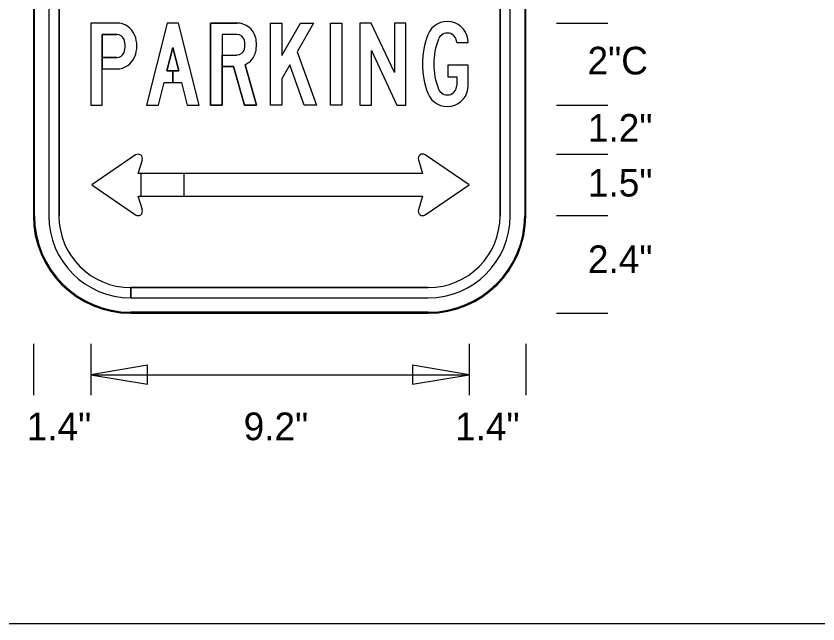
# Model space of a CAD drawing. Extents: x 0 to 770, y 0 to 495.
# Drawn here: x 85.2 to 186.6, y 330 to 406.9 of the extents above; entities that cross this region are included whole.
import ezdxf

# ---------------------------------------------------------------- set-up
doc = ezdxf.new("R2010")
doc.units = 0
for name, color, linetype in [('Dimension', 7, 'Continuous'), ('GSBWFill', 7, 'Continuous'), ('GSColorFill', 7, 'Continuous'), ('GSDims', 7, 'Continuous'), ('GSOutline', 7, 'Continuous'), ('SheetLines_dp', 7, 'Continuous'), ('TextStructures', 7, 'Continuous')]:
    doc.layers.add(name, color=color, linetype=linetype)

msp = doc.modelspace()

# ---------------------------------------------------------------- linework, layer by layer
at = {"layer": 'Dimension'}
for points in [[(94.64, 361.54), (101.81, 360.33), (101.81, 362.76)], [(142.5, 361.54), (135.33, 362.76), (135.33, 360.33)]]:
    msp.add_lwpolyline(points, close=True, dxfattribs=at)
at = {"layer": 'GSBWFill'}
for p, q in [((87.37, 450.45), (87.37, 381.66)), ((89.32, 450.45), (89.32, 381.66)), ((90.62, 381.66), (90.62, 450.45)), ((146.43, 450.45), (146.43, 381.66)), ((147.72, 381.66), (147.72, 450.45)), ((149.67, 381.66), (149.67, 450.45)), ((140.95, 403.6), (142.4, 403.6)), ((113.13, 402.01), (113.13, 402.01)), ((140.95, 399.26), (140.95, 398.14)), ((99.7, 371.28), (99.7, 372.58)), ((137.34, 372.58), (99.71, 372.58)), ((99.71, 372.58), (99.71, 371.28)), ((99.71, 371.28), (137.34, 371.28)), ((99.7, 369.33), (137.34, 369.33))]:
    msp.add_line(p, q, dxfattribs=at)
for points in [[(97.93, 406.06), (94.64, 406.06), (94.64, 395.68), (96.09, 395.68), (96.09, 404.61), (97.93, 404.61)], [(113.13, 404.61), (111.25, 404.61), (111.25, 395.68), (109.8, 395.68), (109.8, 406.06), (113.13, 406.06)], [(114.16, 400.78), (115.61, 395.68), (114.1, 395.68), (112.71, 400.56), (111.25, 400.56), (111.25, 402.01), (113.13, 402.01)], [(97.93, 401.7), (96.09, 401.7), (96.09, 400.25), (97.93, 400.25)], [(142.4, 398.14), (142.4, 400.71), (139.81, 400.71), (139.81, 399.26), (140.95, 399.26)], [(100.3, 389.37), (94.76, 385.57), (100.3, 381.77)], [(106.44, 384.13), (106.44, 387.02), (100.63, 387.02), (101.16, 388.74)], [(136.1, 388.74), (136.63, 387.02), (100.97, 387.02)], [(136.96, 381.78), (142.5, 385.58), (136.96, 389.37)], [(100.97, 387.02), (100.97, 384.13), (136.63, 384.13), (136.1, 382.41)], [(101.16, 382.4), (100.63, 384.13), (106.44, 384.13)]]:
    msp.add_lwpolyline(points, dxfattribs=at)
for points in [[(105.02, 399.99), (104.28, 399.99), (105.02, 402.97), (105.77, 399.99), (105.02, 399.99), (105.02, 398.53), (106.13, 398.53), (106.85, 395.68), (108.34, 395.68), (105.75, 406.06), (104.3, 406.06), (101.7, 395.68), (103.2, 395.68), (103.91, 398.53), (105.02, 398.53)], [(119.83, 400.76), (118.83, 399), (118.83, 395.68), (117.38, 395.68), (117.38, 406.06), (118.83, 406.06), (118.83, 401.95), (121.16, 406.06), (122.83, 406.06), (120.77, 402.43), (123.19, 395.68), (121.65, 395.68)], [(124.96, 406.06), (126.41, 406.06), (126.41, 395.68), (124.96, 395.68)], [(133.37, 395.68), (134.51, 395.68), (134.51, 406.06), (133.06, 406.06), (133.06, 399.79), (130.13, 406.06), (128.7, 406.06), (128.7, 395.68), (130.15, 395.68), (130.15, 402.58)]]:
    msp.add_lwpolyline(points, close=True, dxfattribs=at)
for centre, radius, start, end in [((97.93, 403.62), 2.44, 21.1002, 90), ((139.75, 403.6), 2.65, 0, 158.4314), ((97.93, 403.62), 0.986, 21.1002, 90), ((96.72, 403.15), 2.28, 338.8998, 21.1002), ((96.72, 403.15), 3.74, 338.8998, 21.1002), ((146.65, 400.87), 10.06, 158.4314, 201.5686), ((146.65, 400.87), 8.61, 158.4314, 201.5686), ((139.75, 403.6), 1.19, 0, 158.4314), ((97.93, 402.69), 0.986, 270, 338.8998), ((97.93, 402.69), 2.44, 270, 338.8998), ((139.75, 398.14), 2.65, 201.5686, 0), ((139.75, 398.14), 1.19, 201.5686, 0), ((100.62, 388.9), 0.562, 342.9427, 124.3997), ((136.64, 388.91), 0.562, 55.6003, 197.0573), ((99.7, 381.66), 12.33, 180, 270), ((99.7, 381.66), 10.38, 180, 270), ((99.7, 381.66), 9.09, 180, 270), ((100.62, 382.24), 0.562, 235.6003, 17.0573), ((136.64, 382.25), 0.562, 162.9427, 304.3997), ((137.34, 381.66), 10.38, 270, 0), ((137.34, 381.66), 9.09, 270, 0), ((137.34, 381.66), 12.33, 270, 0)]:
    msp.add_arc(centre, radius, start, end, dxfattribs=at)
for centre, major_axis, start_param, end_param in [((113.13, 403.62), (0, 2.44), 4.954755, 6.283185), ((113.13, 403.62), (0, 0.986), 4.954755, 6.283185), ((111.87, 403.31), (0, 2.28), 4.470023, 4.954755), ((111.87, 403.31), (0, 3.74), 4.470023, 4.954755), ((113.13, 403), (0, 0.986), 3.141593, 4.470023), ((113.13, 403), (0, 2.44), 3.574819, 4.470023)]:
    msp.add_ellipse(centre, major_axis=major_axis, ratio=0.999991, start_param=start_param, end_param=end_param, dxfattribs=at)
at = {"layer": 'GSColorFill'}
for p, q in [((87.37, 450.45), (87.37, 381.66)), ((87.37, 450.45), (87.37, 381.66)), ((87.5, 381.66), (87.5, 450.45)), ((89.32, 450.45), (89.32, 381.66)), ((90.62, 381.66), (90.62, 450.45)), ((146.43, 450.45), (146.43, 381.66)), ((147.72, 381.66), (147.72, 450.45)), ((149.54, 450.45), (149.54, 381.66)), ((149.67, 381.66), (149.67, 450.45)), ((149.67, 381.66), (149.67, 450.45)), ((140.95, 403.6), (142.4, 403.6)), ((113.13, 402.01), (113.13, 402.01)), ((140.95, 399.26), (140.95, 398.14)), ((99.7, 371.28), (99.7, 372.58)), ((137.34, 372.58), (99.71, 372.58)), ((99.71, 372.58), (99.71, 371.28)), ((99.71, 371.28), (137.34, 371.28)), ((99.7, 369.33), (99.7, 369.46)), ((137.34, 369.46), (99.7, 369.46)), ((99.7, 369.46), (99.7, 369.33)), ((99.7, 369.33), (137.34, 369.33)), ((99.7, 369.33), (137.34, 369.33))]:
    msp.add_line(p, q, dxfattribs=at)
for points in [[(97.93, 406.06), (94.64, 406.06), (94.64, 395.68), (96.09, 395.68), (96.09, 404.61), (97.93, 404.61)], [(113.13, 404.61), (111.25, 404.61), (111.25, 395.68), (109.8, 395.68), (109.8, 406.06), (113.13, 406.06)], [(114.16, 400.78), (115.61, 395.68), (114.1, 395.68), (112.71, 400.56), (111.25, 400.56), (111.25, 402.01), (113.13, 402.01)], [(97.93, 401.7), (96.09, 401.7), (96.09, 400.25), (97.93, 400.25)], [(142.4, 398.14), (142.4, 400.71), (139.81, 400.71), (139.81, 399.26), (140.95, 399.26)], [(100.3, 389.37), (94.76, 385.57), (100.3, 381.77)], [(106.44, 384.13), (106.44, 387.02), (100.63, 387.02), (101.16, 388.74)], [(136.1, 388.74), (136.63, 387.02), (100.97, 387.02)], [(136.96, 381.78), (142.5, 385.58), (136.96, 389.37)], [(100.97, 387.02), (100.97, 384.13), (136.63, 384.13), (136.1, 382.41)], [(101.16, 382.4), (100.63, 384.13), (106.44, 384.13)]]:
    msp.add_lwpolyline(points, dxfattribs=at)
for points in [[(105.02, 399.99), (104.28, 399.99), (105.02, 402.97), (105.77, 399.99), (105.02, 399.99), (105.02, 398.53), (106.13, 398.53), (106.85, 395.68), (108.34, 395.68), (105.75, 406.06), (104.3, 406.06), (101.7, 395.68), (103.2, 395.68), (103.91, 398.53), (105.02, 398.53)], [(119.83, 400.76), (118.83, 399), (118.83, 395.68), (117.38, 395.68), (117.38, 406.06), (118.83, 406.06), (118.83, 401.95), (121.16, 406.06), (122.83, 406.06), (120.77, 402.43), (123.19, 395.68), (121.65, 395.68)], [(124.96, 406.06), (126.41, 406.06), (126.41, 395.68), (124.96, 395.68)], [(133.37, 395.68), (134.51, 395.68), (134.51, 406.06), (133.06, 406.06), (133.06, 399.79), (130.13, 406.06), (128.7, 406.06), (128.7, 395.68), (130.15, 395.68), (130.15, 402.58)]]:
    msp.add_lwpolyline(points, close=True, dxfattribs=at)
for centre, radius, start, end in [((97.93, 403.62), 2.44, 21.1002, 90), ((139.75, 403.6), 2.65, 0, 158.4314), ((97.93, 403.62), 0.986, 21.1002, 90), ((96.72, 403.15), 2.28, 338.8998, 21.1002), ((96.72, 403.15), 3.74, 338.8998, 21.1002), ((146.65, 400.87), 10.06, 158.4314, 201.5686), ((146.65, 400.87), 8.61, 158.4314, 201.5686), ((139.75, 403.6), 1.19, 0, 158.4314), ((97.93, 402.69), 0.986, 270, 338.8998), ((97.93, 402.69), 2.44, 270, 338.8998), ((139.75, 398.14), 2.65, 201.5686, 0), ((139.75, 398.14), 1.19, 201.5686, 0), ((100.62, 388.9), 0.562, 342.9427, 124.3997), ((136.64, 388.91), 0.562, 55.6003, 197.0573), ((99.7, 381.66), 12.33, 180, 270), ((99.7, 381.66), 12.33, 180, 270), ((99.7, 381.66), 12.2, 180, 270), ((99.7, 381.66), 10.38, 180, 270), ((99.7, 381.66), 9.09, 180, 270), ((100.62, 382.24), 0.562, 235.6003, 17.0573), ((136.64, 382.25), 0.562, 162.9427, 304.3997), ((137.34, 381.66), 12.33, 270, 0), ((137.34, 381.66), 10.38, 270, 0), ((137.34, 381.66), 9.09, 270, 0), ((137.34, 381.66), 12.33, 270, 0), ((137.34, 381.66), 12.2, 270, 0)]:
    msp.add_arc(centre, radius, start, end, dxfattribs=at)
for centre, major_axis, start_param, end_param in [((113.13, 403.62), (0, 2.44), 4.954755, 6.283185), ((113.13, 403.62), (0, 0.986), 4.954755, 6.283185), ((111.87, 403.31), (0, 2.28), 4.470023, 4.954755), ((111.87, 403.31), (0, 3.74), 4.470023, 4.954755), ((113.13, 403), (0, 0.986), 3.141593, 4.470023), ((113.13, 403), (0, 2.44), 3.574819, 4.470023)]:
    msp.add_ellipse(centre, major_axis=major_axis, ratio=0.999991, start_param=start_param, end_param=end_param, dxfattribs=at)
at = {"layer": 'GSDims'}
for p, q in [((153.56, 406.06), (160.05, 406.06)), ((153.56, 406.06), (160.05, 406.06)), ((153.56, 395.68), (160.05, 395.68)), ((153.56, 395.68), (160.05, 395.68)), ((153.56, 389.47), (160.05, 389.47)), ((153.56, 389.47), (160.05, 389.47)), ((153.56, 381.68), (160.05, 381.68)), ((153.56, 381.68), (160.05, 381.68)), ((153.56, 369.33), (160.05, 369.33)), ((87.37, 365.44), (87.37, 358.95)), ((94.64, 365.44), (94.64, 358.95)), ((94.64, 365.44), (94.64, 358.95)), ((142.5, 365.44), (142.5, 358.95)), ((142.5, 365.44), (142.5, 358.95)), ((149.67, 365.44), (149.67, 358.95)), ((94.64, 361.54), (142.5, 361.54))]:
    msp.add_line(p, q, dxfattribs=at)
at = {"layer": 'GSOutline'}
for p, q in [((87.37, 450.45), (87.37, 381.66)), ((89.32, 450.45), (89.32, 381.66)), ((90.62, 450.45), (90.62, 381.66)), ((146.43, 381.66), (146.43, 450.45)), ((147.72, 381.66), (147.72, 450.45)), ((149.67, 381.66), (149.67, 450.45)), ((97.93, 406.06), (94.64, 406.06)), ((113.13, 406.06), (109.8, 406.06)), ((113.13, 404.61), (113.13, 404.61)), ((140.95, 403.6), (142.4, 403.6)), ((140.95, 399.26), (140.95, 398.14)), ((99.7, 372.58), (137.34, 372.58)), ((99.7, 371.28), (137.34, 371.28)), ((99.7, 369.33), (137.34, 369.33))]:
    msp.add_line(p, q, dxfattribs=at)
for points in [[(94.64, 406.06), (94.64, 395.68), (96.09, 395.68), (96.09, 400.25), (97.93, 400.25)], [(109.8, 406.06), (109.8, 395.68), (111.25, 395.68), (111.25, 400.56), (112.71, 400.56), (114.1, 395.68), (115.61, 395.68), (114.16, 400.78)], [(97.93, 404.61), (96.09, 404.61), (96.09, 401.7), (97.93, 401.7)], [(113.13, 404.61), (111.25, 404.61), (111.25, 402.01), (113.13, 402.01)], [(142.4, 398.14), (142.4, 400.71), (139.81, 400.71), (139.81, 399.26), (140.95, 399.26)], [(100.3, 389.37), (94.76, 385.57), (100.3, 381.77)], [(106.44, 384.13), (106.44, 387.02), (100.63, 387.02), (101.16, 388.74)], [(136.1, 388.74), (136.63, 387.02), (100.97, 387.02)], [(136.96, 381.78), (142.5, 385.58), (136.96, 389.37)], [(100.97, 387.02), (100.97, 384.13), (136.63, 384.13), (136.1, 382.41)], [(101.16, 382.4), (100.63, 384.13), (106.44, 384.13)]]:
    msp.add_lwpolyline(points, dxfattribs=at)
for points in [[(103.91, 398.53), (106.13, 398.53), (106.85, 395.68), (108.34, 395.68), (105.75, 406.06), (104.3, 406.06), (101.7, 395.68), (103.2, 395.68)], [(119.83, 400.76), (118.83, 399), (118.83, 395.68), (117.38, 395.68), (117.38, 406.06), (118.83, 406.06), (118.83, 401.95), (121.16, 406.06), (122.83, 406.06), (120.77, 402.43), (123.19, 395.68), (121.65, 395.68)], [(124.96, 406.06), (126.41, 406.06), (126.41, 395.68), (124.96, 395.68)], [(133.37, 395.68), (134.51, 395.68), (134.51, 406.06), (133.06, 406.06), (133.06, 399.79), (130.13, 406.06), (128.7, 406.06), (128.7, 395.68), (130.15, 395.68), (130.15, 402.58)], [(105.77, 399.99), (105.02, 402.97), (104.28, 399.99)]]:
    msp.add_lwpolyline(points, close=True, dxfattribs=at)
for centre, radius, start, end in [((97.93, 403.62), 2.44, 21.1002, 90), ((139.75, 403.6), 2.65, 0, 158.4314), ((97.93, 403.62), 0.986, 21.1002, 90), ((96.72, 403.15), 2.28, 338.8998, 21.1002), ((96.72, 403.15), 3.74, 338.8998, 21.1002), ((146.65, 400.87), 10.06, 158.4314, 201.5686), ((146.65, 400.87), 8.61, 158.4314, 201.5686), ((139.75, 403.6), 1.19, 0, 158.4314), ((97.93, 402.69), 0.986, 270, 338.8998), ((97.93, 402.69), 2.44, 270, 338.8998), ((139.75, 398.14), 2.65, 201.5686, 0), ((139.75, 398.14), 1.19, 201.5686, 0), ((100.62, 388.9), 0.562, 342.9427, 124.3997), ((136.64, 388.91), 0.562, 55.6003, 197.0573), ((99.7, 381.66), 12.33, 180, 270), ((99.7, 381.66), 10.38, 180, 270), ((99.7, 381.66), 9.09, 180, 270), ((100.62, 382.24), 0.562, 235.6003, 17.0573), ((136.64, 382.25), 0.562, 162.9427, 304.3997), ((137.34, 381.66), 10.38, 270, 0), ((137.34, 381.66), 9.09, 270, 0), ((137.34, 381.66), 12.33, 270, 0)]:
    msp.add_arc(centre, radius, start, end, dxfattribs=at)
for centre, major_axis, start_param, end_param in [((113.13, 403.62), (0, 2.44), 4.954755, 6.283185), ((113.13, 403.62), (0, 0.986), 4.954755, 6.283185), ((111.87, 403.31), (0, 2.28), 4.470023, 4.954755), ((111.87, 403.31), (0, 3.74), 4.470023, 4.954755), ((113.13, 403), (0, 0.986), 3.141593, 4.470023), ((113.13, 403), (0, 2.44), 3.574819, 4.470023)]:
    msp.add_ellipse(centre, major_axis=major_axis, ratio=0.999991, start_param=start_param, end_param=end_param, dxfattribs=at)
at = {"layer": 'SheetLines_dp'}
msp.add_line((770, 330), (0, 330), dxfattribs=at)

# ---------------------------------------------------------------- texts
at = {"layer": 'TextStructures'}
for s, p in [('2"C', (157.49, 399.55)), ('1.2"', (157.54, 391.04)), ('1.5"', (157.54, 384.1)), ('2.4"', (157.54, 374.41)), ('1.4"', (86.53, 353.26)), ('9.2"', (113.98, 353.26)), ('1.4"', (140.73, 353.26))]:
    msp.add_text(s, height=3.5, dxfattribs=at).set_placement(p)

doc.saveas('drawing.dxf')
